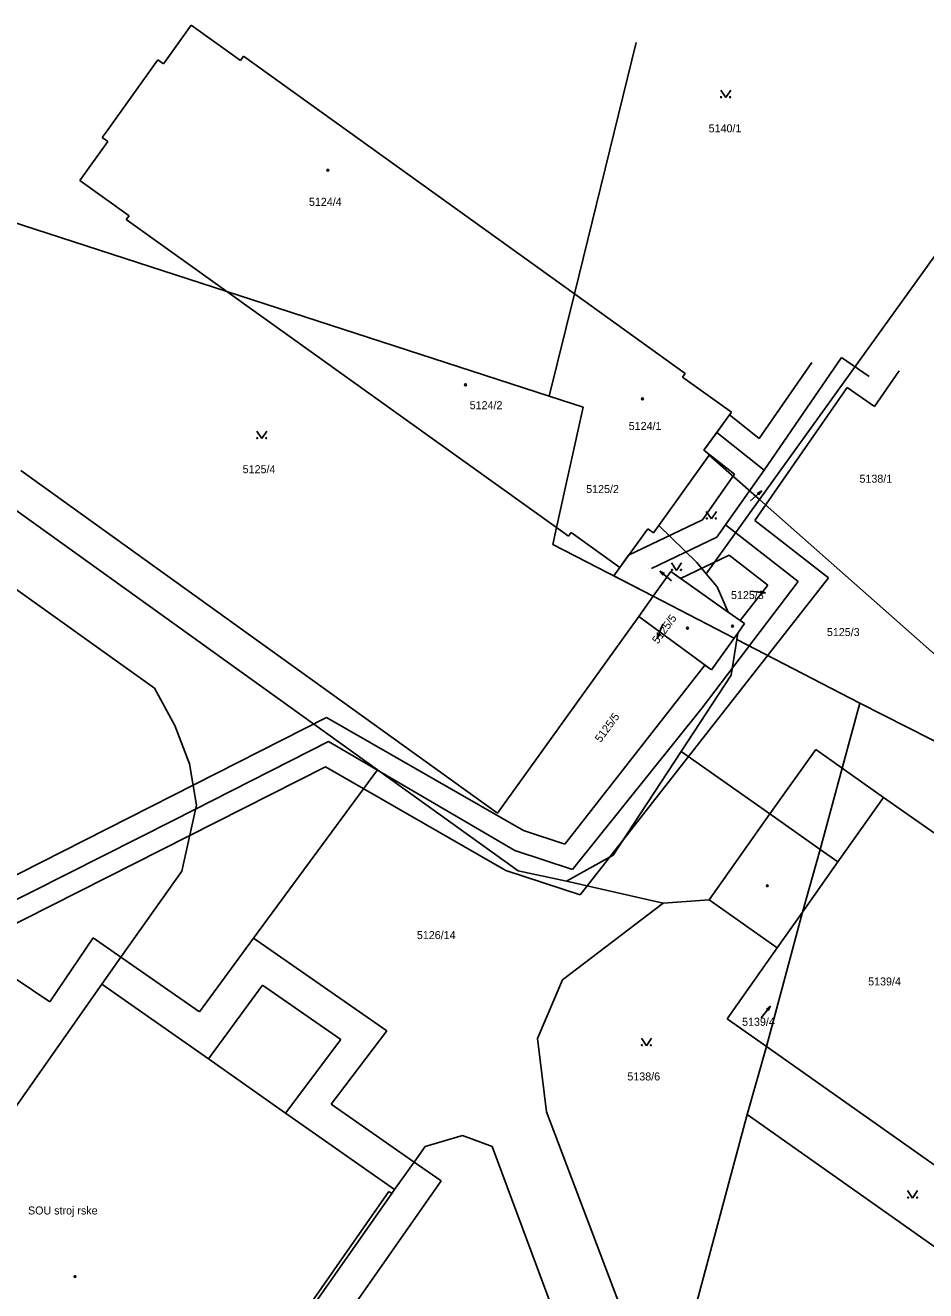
# Model space of a CAD drawing. Extents: x -400488 to -400124, y -1251493 to -1251223.
# Drawn here: x -400451.9 to -400397.9, y -1251299.4 to -1251223.4 of the extents above; entities that cross this region are included whole.
import ezdxf

# ---------------------------------------------------------------- set-up
doc = ezdxf.new("R2010")
doc.units = 0
doc.layers.add('Level 63', color=7, linetype='Continuous')

msp = doc.modelspace()

# ---------------------------------------------------------------- linework, layer by layer
at = {"layer": 'Level 63'}
for p, q in [((-400443.56, -1251225.67), (-400441.96, -1251223.44)), ((-400441.96, -1251223.44), (-400443.56, -1251225.67)), ((-400441.96, -1251223.44), (-400439.01, -1251225.55)), ((-400439.01, -1251225.55), (-400441.96, -1251223.44)), ((-400418.98, -1251239.55), (-400415.28, -1251224.48)), ((-400415.28, -1251224.48), (-400418.98, -1251239.55)), ((-400447.07, -1251229.85), (-400443.97, -1251225.52)), ((-400443.97, -1251225.52), (-400447.07, -1251229.85)), ((-400443.97, -1251225.52), (-400443.62, -1251225.76)), ((-400443.62, -1251225.76), (-400443.97, -1251225.52)), ((-400439.01, -1251225.55), (-400438.83, -1251225.3)), ((-400438.83, -1251225.3), (-400439.01, -1251225.55)), ((-400438.83, -1251225.3), (-400418.98, -1251239.55)), ((-400418.98, -1251239.55), (-400438.83, -1251225.3)), ((-400443.62, -1251225.76), (-400443.56, -1251225.67)), ((-400443.56, -1251225.67), (-400443.62, -1251225.76)), ((-400410.21, -1251227.33), (-400409.91, -1251227.78)), ((-400409.91, -1251227.78), (-400409.61, -1251227.33)), ((-400447.31, -1251230.18), (-400447.07, -1251229.85)), ((-400447.07, -1251229.85), (-400447.31, -1251230.18)), ((-400448.64, -1251232.75), (-400446.97, -1251230.42)), ((-400446.97, -1251230.42), (-400448.64, -1251232.75)), ((-400446.97, -1251230.42), (-400447.31, -1251230.18)), ((-400447.31, -1251230.18), (-400446.97, -1251230.42)), ((-400407.88, -1251251.89), (-400392.51, -1251230.5)), ((-400392.51, -1251230.5), (-400407.88, -1251251.89)), ((-400445.69, -1251234.86), (-400448.64, -1251232.75)), ((-400448.64, -1251232.75), (-400445.69, -1251234.86)), ((-400456.8, -1251233.9), (-400439.83, -1251239.41)), ((-400439.83, -1251239.41), (-400456.8, -1251233.9)), ((-400445.86, -1251235.09), (-400445.69, -1251234.86)), ((-400445.69, -1251234.86), (-400445.86, -1251235.09)), ((-400439.83, -1251239.41), (-400445.86, -1251235.09)), ((-400445.86, -1251235.09), (-400439.83, -1251239.41)), ((-400420.06, -1251253.57), (-400439.83, -1251239.41)), ((-400439.83, -1251239.41), (-400420.49, -1251245.69)), ((-400439.83, -1251239.41), (-400420.06, -1251253.57)), ((-400420.49, -1251245.69), (-400439.83, -1251239.41)), ((-400418.98, -1251239.55), (-400420.49, -1251245.69)), ((-400420.49, -1251245.69), (-400418.98, -1251239.55)), ((-400418.98, -1251239.55), (-400412.33, -1251244.33)), ((-400412.33, -1251244.33), (-400418.98, -1251239.55)), ((-400407.91, -1251248.22), (-400404.75, -1251243.66)), ((-400402.96, -1251243.36), (-400407.6, -1251250.12)), ((-400402.96, -1251243.36), (-400401.31, -1251244.5)), ((-400412.33, -1251244.33), (-400412.5, -1251244.55)), ((-400412.5, -1251244.55), (-400412.33, -1251244.33)), ((-400399.51, -1251244.17), (-400400.98, -1251246.31)), ((-400412.5, -1251244.55), (-400409.57, -1251246.65)), ((-400409.57, -1251246.65), (-400412.5, -1251244.55)), ((-400402.63, -1251245.17), (-400408.16, -1251253.14)), ((-400400.98, -1251246.31), (-400402.63, -1251245.17)), ((-400420.49, -1251245.69), (-400418.46, -1251246.35)), ((-400418.46, -1251246.35), (-400420.49, -1251245.69)), ((-400418.46, -1251246.35), (-400420.06, -1251253.57)), ((-400420.06, -1251253.57), (-400418.46, -1251246.35)), ((-400409.57, -1251246.65), (-400411.21, -1251248.93)), ((-400411.21, -1251248.93), (-400409.57, -1251246.65)), ((-400460.13, -1251247.03), (-400430.79, -1251268.11)), ((-400410.45, -1251247.87), (-400409.69, -1251246.81)), ((-400409.69, -1251246.81), (-400407.91, -1251248.22)), ((-400438.03, -1251247.78), (-400437.73, -1251248.23)), ((-400437.73, -1251248.23), (-400437.43, -1251247.78)), ((-400411.21, -1251248.93), (-400410.45, -1251247.87)), ((-400407.6, -1251250.12), (-400410.45, -1251247.87)), ((-400409.39, -1251250.36), (-400411.21, -1251248.93)), ((-400411.21, -1251248.93), (-400410.89, -1251249.22)), ((-400410.89, -1251249.22), (-400411.21, -1251248.93)), ((-400413.92, -1251253.44), (-400410.89, -1251249.22)), ((-400410.89, -1251249.22), (-400413.92, -1251253.44)), ((-400410.89, -1251249.22), (-400407.88, -1251251.89)), ((-400407.88, -1251251.89), (-400410.89, -1251249.22)), ((-400423.59, -1251270.7), (-400452.17, -1251250.15)), ((-400452.17, -1251250.15), (-400423.59, -1251270.7)), ((-400411.3, -1251253.11), (-400409.39, -1251250.36)), ((-400407.6, -1251250.12), (-400409.92, -1251253.41)), ((-400461.15, -1251251.07), (-400444.17, -1251263.21)), ((-400407.88, -1251251.89), (-400411.08, -1251256.34)), ((-400411.08, -1251256.34), (-400407.88, -1251251.89)), ((-400408.42, -1251251.97), (-400407.749, -1251251.371)), ((-400407.749, -1251251.371), (-400408.012, -1251251.526)), ((-400407.932, -1251251.615), (-400407.749, -1251251.371)), ((-400407.88, -1251251.89), (-400395.04, -1251263.25)), ((-400395.04, -1251263.25), (-400407.88, -1251251.89)), ((-400411.07, -1251252.6), (-400410.77, -1251253.05)), ((-400410.77, -1251253.05), (-400410.47, -1251252.6)), ((-400420.28, -1251254.58), (-400420.06, -1251253.57)), ((-400420.06, -1251253.57), (-400420.28, -1251254.58)), ((-400420.06, -1251253.57), (-400419.34, -1251254.09)), ((-400419.34, -1251254.09), (-400420.06, -1251253.57)), ((-400415.73, -1251255.23), (-400411.3, -1251253.11)), ((-400414.24, -1251253.88), (-400413.92, -1251253.44)), ((-400413.92, -1251253.44), (-400414.24, -1251253.88)), ((-400413.92, -1251253.44), (-400411.63, -1251255.67)), ((-400411.63, -1251255.67), (-400413.92, -1251253.44)), ((-400409.92, -1251253.41), (-400410.44, -1251254.14)), ((-400409.92, -1251253.41), (-400405.57, -1251256.8)), ((-400408.16, -1251253.14), (-400403.74, -1251256.58)), ((-400419.34, -1251254.09), (-400419.17, -1251253.87)), ((-400419.17, -1251253.87), (-400419.34, -1251254.09)), ((-400419.17, -1251253.87), (-400416.25, -1251255.96)), ((-400416.25, -1251255.96), (-400419.17, -1251253.87)), ((-400416.25, -1251255.96), (-400414.58, -1251253.64)), ((-400414.58, -1251253.64), (-400416.25, -1251255.96)), ((-400414.58, -1251253.64), (-400414.24, -1251253.88)), ((-400414.24, -1251253.88), (-400414.58, -1251253.64)), ((-400410.44, -1251254.14), (-400414.36, -1251256.02)), ((-400414.26, -1251257.69), (-400420.28, -1251254.58)), ((-400420.28, -1251254.58), (-400414.26, -1251257.69)), ((-400416.25, -1251255.96), (-400415.73, -1251255.23)), ((-400413.16, -1251255.69), (-400412.86, -1251256.14)), ((-400412.86, -1251256.14), (-400412.56, -1251255.69)), ((-400409.7, -1251255.23), (-400412.61, -1251256.62)), ((-400411.63, -1251255.67), (-400411.08, -1251256.34)), ((-400411.08, -1251256.34), (-400411.63, -1251255.67)), ((-400407.39, -1251257.03), (-400409.7, -1251255.23)), ((-400403.74, -1251256.58), (-400418.64, -1251275.61)), ((-400416.62, -1251256.47), (-400416.25, -1251255.96)), ((-400414.26, -1251257.69), (-400416.62, -1251256.47)), ((-400413.2, -1251256.2), (-400414.26, -1251257.69)), ((-400414.26, -1251257.69), (-400413.2, -1251256.2)), ((-400413.2, -1251256.2), (-400414.26, -1251257.69)), ((-400413.16, -1251256.76), (-400413.849, -1251256.18)), ((-400413.849, -1251256.18), (-400413.658, -1251256.42)), ((-400413.58, -1251256.328), (-400413.849, -1251256.18)), ((-400409.76, -1251258.64), (-400413.2, -1251256.2)), ((-400413.2, -1251256.2), (-400409.76, -1251258.64)), ((-400412.61, -1251256.62), (-400413.2, -1251256.2)), ((-400411.08, -1251256.34), (-400410.43, -1251257.13)), ((-400410.43, -1251257.13), (-400411.08, -1251256.34)), ((-400405.57, -1251256.8), (-400411.32, -1251264.38)), ((-400410.43, -1251257.13), (-400409.76, -1251258.64)), ((-400409.76, -1251258.64), (-400410.43, -1251257.13)), ((-400409.05, -1251259.14), (-400407.39, -1251257.03)), ((-400408.42, -1251257.38), (-400407.526, -1251257.484)), ((-400407.526, -1251257.484), (-400407.817, -1251257.39)), ((-400415.12, -1251258.91), (-400414.26, -1251257.69)), ((-400414.26, -1251257.69), (-400415.12, -1251258.91)), ((-400414.26, -1251257.69), (-400409.4, -1251260.2)), ((-400409.4, -1251260.2), (-400414.26, -1251257.69)), ((-400407.831, -1251257.509), (-400407.526, -1251257.484)), ((-400415.12, -1251258.91), (-400423.59, -1251270.7)), ((-400423.59, -1251270.7), (-400415.12, -1251258.91)), ((-400410.77, -1251262.1), (-400415.12, -1251258.91)), ((-400415.12, -1251258.91), (-400410.77, -1251262.1)), ((-400409.76, -1251258.64), (-400408.78, -1251259.33)), ((-400408.78, -1251259.33), (-400409.76, -1251258.64)), ((-400413.68, -1251259.37), (-400414.014, -1251260.206)), ((-400408.78, -1251259.33), (-400409.19, -1251259.91)), ((-400409.19, -1251259.91), (-400408.78, -1251259.33)), ((-400409.19, -1251259.91), (-400408.78, -1251259.33)), ((-400408.78, -1251259.33), (-400409.05, -1251259.14)), ((-400413.959, -1251259.905), (-400414.014, -1251260.206)), ((-400414.014, -1251260.206), (-400413.847, -1251259.949)), ((-400409.4, -1251260.2), (-400410.77, -1251262.1)), ((-400410.77, -1251262.1), (-400409.4, -1251260.2)), ((-400410.77, -1251262.1), (-400409.4, -1251260.2)), ((-400409.59, -1251262.43), (-400409.25, -1251260.28)), ((-400409.19, -1251259.91), (-400409.4, -1251260.2)), ((-400409.4, -1251260.2), (-400409.19, -1251259.91)), ((-400409.4, -1251260.2), (-400409.19, -1251259.91)), ((-400409.25, -1251260.28), (-400409.19, -1251259.91)), ((-400409.19, -1251259.91), (-400409.25, -1251260.28)), ((-400401.86, -1251264.1), (-400409.25, -1251260.28)), ((-400409.25, -1251260.28), (-400401.86, -1251264.1)), ((-400419.56, -1251272.57), (-400411.15, -1251261.82)), ((-400411.15, -1251261.82), (-400410.77, -1251262.1)), ((-400412.58, -1251267), (-400409.59, -1251262.43)), ((-400444.17, -1251263.21), (-400442.95, -1251265.44)), ((-400402.92, -1251268.01), (-400401.86, -1251264.1)), ((-400401.86, -1251264.1), (-400402.92, -1251268.01)), ((-400401.86, -1251264.1), (-400369.97, -1251280.4)), ((-400369.97, -1251280.4), (-400401.86, -1251264.1)), ((-400472, -1251284.31), (-400433.84, -1251264.97)), ((-400433.84, -1251264.97), (-400422.03, -1251271.75)), ((-400411.32, -1251264.38), (-400419.1, -1251274.09)), ((-400442.95, -1251265.44), (-400442.06, -1251267.75)), ((-400433.73, -1251266.4), (-400443.01, -1251271.13)), ((-400422.56, -1251272.94), (-400433.73, -1251266.4)), ((-400416.65, -1251273.22), (-400412.58, -1251267)), ((-400412.58, -1251267), (-400416.65, -1251273.22)), ((-400412.58, -1251267), (-400407.26, -1251270.75)), ((-400407.26, -1251270.75), (-400412.58, -1251267)), ((-400407.26, -1251270.75), (-400404.51, -1251266.88)), ((-400404.51, -1251266.88), (-400402.92, -1251268.01)), ((-400433.91, -1251267.92), (-400472.18, -1251287.31)), ((-400442.06, -1251267.75), (-400441.65, -1251270.23)), ((-400423.09, -1251274.14), (-400433.91, -1251267.92)), ((-400404.24, -1251272.88), (-400402.92, -1251268.01)), ((-400402.92, -1251268.01), (-400404.24, -1251272.88)), ((-400402.92, -1251268.01), (-400400.44, -1251269.76)), ((-400438.22, -1251278.21), (-400430.79, -1251268.11)), ((-400430.79, -1251268.11), (-400438.22, -1251278.21)), ((-400430.79, -1251268.11), (-400422.36, -1251274.17)), ((-400422.36, -1251274.17), (-400430.79, -1251268.11)), ((-400441.65, -1251270.23), (-400442.53, -1251274.19)), ((-400400.44, -1251269.76), (-400403.18, -1251273.63)), ((-400403.18, -1251273.63), (-400400.44, -1251269.76)), ((-400394.6, -1251273.88), (-400400.44, -1251269.76)), ((-400400.44, -1251269.76), (-400394.6, -1251273.88)), ((-400407.26, -1251270.75), (-400410.89, -1251275.91)), ((-400410.89, -1251275.91), (-400407.26, -1251270.75)), ((-400407.26, -1251270.75), (-400404.24, -1251272.88)), ((-400404.24, -1251272.88), (-400407.26, -1251270.75)), ((-400443.01, -1251271.13), (-400472.14, -1251285.84)), ((-400466.3, -1251271.38), (-400450.44, -1251282.03)), ((-400450.44, -1251282.03), (-400466.3, -1251271.38)), ((-400422.03, -1251271.75), (-400419.56, -1251272.57)), ((-400419.1, -1251274.09), (-400422.56, -1251272.94)), ((-400419.46, -1251274.78), (-400416.65, -1251273.22)), ((-400416.65, -1251273.22), (-400419.46, -1251274.78)), ((-400404.24, -1251272.88), (-400405.3, -1251276.64)), ((-400405.3, -1251276.64), (-400404.24, -1251272.88)), ((-400403.18, -1251273.63), (-400404.24, -1251272.88)), ((-400404.24, -1251272.88), (-400403.18, -1251273.63)), ((-400405.3, -1251276.64), (-400403.18, -1251273.63)), ((-400442.53, -1251274.19), (-400446.18, -1251279.35)), ((-400418.64, -1251275.61), (-400423.09, -1251274.14)), ((-400422.36, -1251274.17), (-400419.46, -1251274.78)), ((-400419.46, -1251274.78), (-400422.36, -1251274.17)), ((-400419.46, -1251274.78), (-400413.66, -1251276.1)), ((-400413.66, -1251276.1), (-400419.7, -1251280.71)), ((-400419.7, -1251280.71), (-400413.66, -1251276.1)), ((-400410.89, -1251275.91), (-400413.66, -1251276.1)), ((-400413.66, -1251276.1), (-400410.89, -1251275.91)), ((-400410.89, -1251275.91), (-400406.82, -1251278.78)), ((-400406.82, -1251278.78), (-400410.89, -1251275.91)), ((-400405.3, -1251276.64), (-400407.46, -1251284.71)), ((-400407.46, -1251284.71), (-400405.3, -1251276.64)), ((-400406.82, -1251278.78), (-400405.3, -1251276.64)), ((-400450.44, -1251282.03), (-400447.85, -1251278.18)), ((-400447.85, -1251278.18), (-400450.44, -1251282.03)), ((-400447.85, -1251278.18), (-400446.18, -1251279.35)), ((-400446.18, -1251279.35), (-400447.85, -1251278.18)), ((-400441.47, -1251282.63), (-400438.22, -1251278.21)), ((-400438.22, -1251278.21), (-400441.47, -1251282.63)), ((-400430.23, -1251283.76), (-400438.22, -1251278.21)), ((-400438.22, -1251278.21), (-400430.23, -1251283.76)), ((-400446.18, -1251279.35), (-400447.32, -1251280.96)), ((-400446.18, -1251279.35), (-400441.47, -1251282.63)), ((-400441.47, -1251282.63), (-400446.18, -1251279.35)), ((-400406.82, -1251278.78), (-400409.83, -1251283.04)), ((-400409.83, -1251283.04), (-400406.82, -1251278.78)), ((-400419.7, -1251280.71), (-400421.19, -1251284.22)), ((-400421.19, -1251284.22), (-400419.7, -1251280.71)), ((-400447.32, -1251280.96), (-400457.89, -1251296.01)), ((-400457.89, -1251296.01), (-400447.32, -1251280.96)), ((-400440.93, -1251285.45), (-400447.32, -1251280.96)), ((-400447.32, -1251280.96), (-400440.93, -1251285.45)), ((-400437.68, -1251281.02), (-400440.93, -1251285.45)), ((-400440.93, -1251285.45), (-400437.68, -1251281.02)), ((-400432.98, -1251284.29), (-400437.68, -1251281.02)), ((-400437.68, -1251281.02), (-400432.98, -1251284.29)), ((-400407.79, -1251282.98), (-400407.226, -1251282.279)), ((-400407.226, -1251282.279), (-400407.461, -1251282.475)), ((-400407.367, -1251282.55), (-400407.226, -1251282.279)), ((-400409.83, -1251283.04), (-400407.46, -1251284.71)), ((-400407.46, -1251284.71), (-400409.83, -1251283.04)), ((-400433.57, -1251288.17), (-400430.23, -1251283.76)), ((-400430.23, -1251283.76), (-400433.57, -1251288.17)), ((-400436.31, -1251288.7), (-400432.98, -1251284.29)), ((-400432.98, -1251284.29), (-400436.31, -1251288.7)), ((-400421.19, -1251284.22), (-400420.65, -1251288.62)), ((-400420.65, -1251288.62), (-400421.19, -1251284.22)), ((-400414.96, -1251284.21), (-400414.66, -1251284.66)), ((-400414.66, -1251284.66), (-400414.36, -1251284.21)), ((-400407.46, -1251284.71), (-400408.63, -1251288.78)), ((-400408.63, -1251288.78), (-400407.46, -1251284.71)), ((-400407.46, -1251284.71), (-400376.45, -1251306.6)), ((-400376.45, -1251306.6), (-400407.46, -1251284.71)), ((-400440.93, -1251285.45), (-400436.31, -1251288.7)), ((-400428.6, -1251291.64), (-400433.57, -1251288.17)), ((-400433.57, -1251288.17), (-400428.6, -1251291.64)), ((-400429.77, -1251293.29), (-400436.31, -1251288.7)), ((-400436.31, -1251288.7), (-400429.77, -1251293.29)), ((-400420.65, -1251288.62), (-400413.58, -1251307.27)), ((-400413.58, -1251307.27), (-400420.65, -1251288.62)), ((-400408.63, -1251288.78), (-400413.58, -1251307.27)), ((-400413.58, -1251307.27), (-400408.63, -1251288.78)), ((-400408.63, -1251288.78), (-400377.14, -1251311.01)), ((-400377.14, -1251311.01), (-400408.63, -1251288.78)), ((-400425.69, -1251290.05), (-400427.93, -1251290.7)), ((-400427.93, -1251290.7), (-400425.69, -1251290.05)), ((-400423.92, -1251290.71), (-400425.69, -1251290.05)), ((-400425.69, -1251290.05), (-400423.92, -1251290.71)), ((-400427.93, -1251290.7), (-400428.6, -1251291.64)), ((-400428.6, -1251291.64), (-400427.93, -1251290.7)), ((-400418.99, -1251303.93), (-400423.92, -1251290.71)), ((-400423.92, -1251290.71), (-400418.99, -1251303.93)), ((-400428.6, -1251291.64), (-400429.77, -1251293.29)), ((-400428.6, -1251291.64), (-400426.97, -1251292.77)), ((-400426.97, -1251292.77), (-400428.6, -1251291.64)), ((-400426.97, -1251292.77), (-400437.31, -1251307.53)), ((-400437.31, -1251307.53), (-400426.97, -1251292.77)), ((-400440.52, -1251308.27), (-400430.11, -1251293.41)), ((-400430.11, -1251293.41), (-400440.52, -1251308.27)), ((-400429.94, -1251293.53), (-400440.34, -1251308.34)), ((-400430.11, -1251293.41), (-400429.94, -1251293.53)), ((-400429.94, -1251293.53), (-400430.11, -1251293.41)), ((-400429.94, -1251293.53), (-400429.77, -1251293.29)), ((-400429.77, -1251293.29), (-400429.94, -1251293.53)), ((-400399, -1251293.35), (-400398.7, -1251293.8)), ((-400398.7, -1251293.8), (-400398.4, -1251293.35))]:
    msp.add_line(p, q, dxfattribs=at)
for centre, radius in [((-400410.18, -1251227.75), 0.03), ((-400409.64, -1251227.75), 0.03), ((-400433.77, -1251232.136), 0.054), ((-400425.51, -1251245.006), 0.054), ((-400414.9, -1251245.846), 0.054), ((-400438, -1251248.2), 0.03), ((-400437.46, -1251248.2), 0.03), ((-400411.04, -1251253.02), 0.03), ((-400410.5, -1251253.02), 0.03), ((-400413.13, -1251256.11), 0.03), ((-400412.59, -1251256.11), 0.03), ((-400412.2, -1251259.606), 0.054), ((-400409.5, -1251259.486), 0.054), ((-400407.41, -1251275.056), 0.054), ((-400414.93, -1251284.63), 0.03), ((-400414.39, -1251284.63), 0.03), ((-400398.97, -1251293.77), 0.03), ((-400398.43, -1251293.77), 0.03), ((-400448.93, -1251298.506), 0.054)]:
    msp.add_circle(centre, radius, dxfattribs=at)

# ---------------------------------------------------------------- texts
for s, p in [('5140/1', (-400410.93, -1251229.86)), ('5124/4', (-400434.902, -1251234.27)), ('5124/2', (-400425.262, -1251246.47)), ('5124/1', (-400415.724, -1251247.72)), ('5125/4', (-400438.875, -1251250.31)), ('5138/1', (-400401.885, -1251250.88)), ('5125/2', (-400418.276, -1251251.5)), ('5125/3', (-400409.59, -1251257.86)), ('5125/3', (-400403.84, -1251260.08)), ('5126/14', (-400428.428, -1251278.26)), ('5139/4', (-400401.366, -1251281.04)), ('5139/4', (-400408.926, -1251283.46)), ('5138/6', (-400415.803, -1251286.74)), ('SOU stroj\xa0rske', (-400451.75, -1251294.78))]:
    msp.add_text(s, height=0.48, dxfattribs=at).set_placement(p)
for p in [(-400413.979, -1251260.587), (-400417.409, -1251266.497)]:
    msp.add_text('5125/5', height=0.48, rotation=53.67, dxfattribs=at).set_placement(p)

doc.saveas('drawing.dxf')
